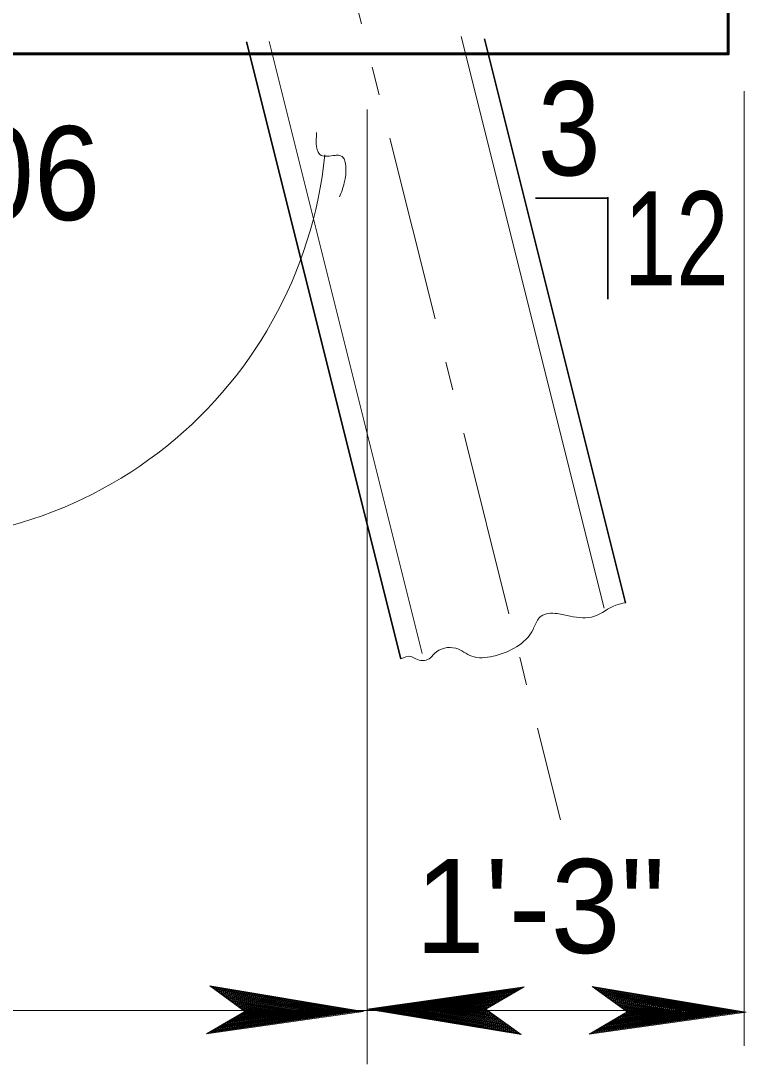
# Model space of a CAD drawing. Extents: x 144 to 252, y 360 to 425.
# Drawn here: x 195.351 to 197.883, y 388.875 to 392.519 of the extents above; entities that cross this region are included whole.
import ezdxf
from ezdxf.enums import TextEntityAlignment as Align

# ---------------------------------------------------------------- set-up
doc = ezdxf.new("R2010")
doc.units = 0
doc.header["$LTSCALE"] = 0.13
doc.linetypes.add('DOT_DASHED', pattern=[7.7, 5, -1.2, 0.3, -1.2])
for name, color, linetype, lineweight in [('1', 7, 'Continuous', 40), ('14', 7, 'Continuous', 13), ('16', 7, 'Continuous', 13), ('3', 7, 'Continuous', 13), ('5', 7, 'Continuous', 35)]:
    doc.layers.add(name, color=color, linetype=linetype, lineweight=lineweight)

msp = doc.modelspace()

# ---------------------------------------------------------------- linework, layer by layer
at = {"layer": '1', "lineweight": 60}
msp.add_lwpolyline([(189.8208, 392.4032), (197.8208, 392.4032), (197.8208, 394.4032), (194.0708, 394.4032), (194.0708, 394.6532), (193.5708, 394.6532), (193.5708, 394.4032), (189.8208, 394.4032)], dxfattribs=at)
at = {"layer": '16', "lineweight": 35}
for p, q in [((197.1477, 391.8999), (197.3977, 391.8999)), ((197.4002, 391.9027), (197.4002, 391.5464))]:
    msp.add_line(p, q, dxfattribs=at)
at = {"layer": '16'}
msp.add_arc((194.9206, 392.2022), 1.4992, 260.3949, 354.2102, dxfattribs=at)
msp.add_spline([(196.4637, 391.9044), (196.4797, 391.9526), (196.4637, 392.0489), (196.4476, 392.0489), (196.3994, 392.0489), (196.3833, 392.1293)], degree=3, dxfattribs=at)
at = {"layer": '3'}
for p, q in [((197.8766, 388.9398), (197.8766, 392.2738)), ((196.56, 388.8755), (196.56, 392.2095)), ((196.5476, 389.0595), (196.0099, 389.1488)), ((196.0099, 389.1488), (196.1324, 389.0597)), ((196.5332, 389.0602), (196.0132, 389.1464)), ((196.5223, 389.0602), (196.0164, 389.1441)), ((196.5079, 389.0602), (196.0207, 389.1409)), ((197.1083, 389.1457), (196.5596, 389.0679)), ((197.1023, 389.1422), (196.574, 389.0673)), ((196.9748, 389.0677), (197.1083, 389.1457)), ((197.8834, 389.0574), (197.3457, 389.1467)), ((197.3457, 389.1467), (197.4682, 389.0576)), ((197.869, 389.0581), (197.349, 389.1443)), ((197.8582, 389.0581), (197.3522, 389.142)), ((196.4952, 389.0602), (196.0244, 389.1382)), ((196.4838, 389.0602), (196.0277, 389.1358)), ((196.4694, 389.0602), (196.032, 389.1327)), ((196.4567, 389.0602), (196.0358, 389.1299)), ((196.4429, 389.0602), (196.0398, 389.127)), ((196.4291, 389.0602), (196.0439, 389.124)), ((196.4158, 389.0602), (196.0478, 389.1212)), ((196.4019, 389.0602), (196.0519, 389.1182)), ((196.3893, 389.0602), (196.0557, 389.1155)), ((196.3779, 389.0602), (196.0591, 389.113)), ((196.3622, 389.0602), (196.0637, 389.1097)), ((196.3484, 389.0602), (196.0677, 389.1067)), ((197.0988, 389.1402), (196.5848, 389.0673)), ((197.0942, 389.1375), (196.5992, 389.0673)), ((197.0902, 389.1351), (196.612, 389.0673)), ((197.0902, 389.1351), (196.612, 389.0673)), ((197.0865, 389.1329), (196.6233, 389.0673)), ((197.0819, 389.1302), (196.6377, 389.0673)), ((197.0778, 389.1278), (196.6505, 389.0673)), ((197.0734, 389.1253), (196.6642, 389.0673)), ((197.069, 389.1227), (196.6781, 389.0673)), ((197.0648, 389.1202), (196.6913, 389.0673)), ((197.0602, 389.1176), (196.7053, 389.0673)), ((197.0563, 389.1153), (196.7178, 389.0673)), ((197.0525, 389.1131), (196.7293, 389.0673)), ((197.0475, 389.1103), (196.7449, 389.0673)), ((197.0431, 389.1076), (196.7587, 389.0673)), ((197.0391, 389.1053), (196.7783, 389.0683)), ((197.8438, 389.0581), (197.3565, 389.1388)), ((197.831, 389.0581), (197.3602, 389.1362)), ((197.8197, 389.0581), (197.3636, 389.1337)), ((197.8053, 389.0581), (197.3678, 389.1306)), ((197.7925, 389.0581), (197.3716, 389.1278)), ((197.7788, 389.0581), (197.3757, 389.1249)), ((197.7649, 389.0581), (197.3798, 389.1219)), ((197.7517, 389.0581), (197.3837, 389.1191)), ((197.7378, 389.0581), (197.3877, 389.1161)), ((197.7252, 389.0581), (197.3915, 389.1134)), ((197.7138, 389.0581), (197.3949, 389.1109)), ((197.6981, 389.0581), (197.3995, 389.1076)), ((197.6842, 389.0581), (197.4036, 389.1046)), ((196.3304, 389.0607), (196.072, 389.1036)), ((196.3165, 389.0607), (196.0762, 389.1006)), ((196.3033, 389.0607), (196.08, 389.0977)), ((196.2943, 389.0602), (196.0837, 389.095)), ((196.2823, 389.0602), (196.0873, 389.0924)), ((196.2684, 389.0602), (196.0914, 389.0894)), ((196.2527, 389.0602), (196.0961, 389.0862)), ((196.2402, 389.0602), (196.0998, 389.0834)), ((196.2269, 389.0602), (196.1037, 389.0806)), ((196.2149, 389.0602), (196.1072, 389.0779)), ((196.2004, 389.0602), (196.1115, 389.0749)), ((196.1866, 389.0602), (196.1157, 389.0719)), ((196.1739, 389.0602), (196.1193, 389.0692)), ((197.0359, 389.1034), (196.7767, 389.0668)), ((197.0315, 389.1008), (196.7907, 389.0668)), ((197.0272, 389.0983), (196.8038, 389.0668)), ((197.0257, 389.0975), (196.8129, 389.0673)), ((197.0218, 389.0952), (196.8249, 389.0673)), ((197.0174, 389.0926), (196.8388, 389.0673)), ((197.0124, 389.0897), (196.8544, 389.0673)), ((197.0083, 389.0873), (196.867, 389.0673)), ((197.0041, 389.0848), (196.8802, 389.0673)), ((197.0002, 389.0826), (196.8922, 389.0673)), ((196.9956, 389.0799), (196.9067, 389.0673)), ((196.9912, 389.0773), (196.9206, 389.0673)), ((196.9871, 389.075), (196.9332, 389.0673)), ((196.9818, 389.0719), (196.9567, 389.0683)), ((196.9792, 389.0703), (196.9579, 389.0673)), ((197.6662, 389.0586), (197.4078, 389.1015)), ((197.6523, 389.0586), (197.412, 389.0985)), ((197.6392, 389.0586), (197.4158, 389.0957)), ((197.6301, 389.0581), (197.4196, 389.0929)), ((197.6181, 389.0581), (197.4232, 389.0903)), ((197.6043, 389.0581), (197.4272, 389.0873)), ((197.5886, 389.0581), (197.4319, 389.0841)), ((197.576, 389.0581), (197.4356, 389.0813)), ((197.5627, 389.0581), (197.4395, 389.0785)), ((197.5507, 389.0581), (197.4431, 389.0758)), ((197.5362, 389.0581), (197.4473, 389.0728)), ((197.5224, 389.0581), (197.4515, 389.0698)), ((195.8124, 389.0625), (189.8297, 389.0625)), ((197.8124, 389.0625), (191.8297, 389.0625)), ((196.1324, 389.0597), (195.9988, 388.9817)), ((195.9988, 388.9817), (196.5476, 389.0595)), ((196.0048, 388.9853), (196.5332, 389.0602)), ((196.0083, 388.9872), (196.5223, 389.0602)), ((196.0129, 388.9899), (196.5079, 389.0602)), ((196.017, 388.9923), (196.4952, 389.0602)), ((196.017, 388.9923), (196.4952, 389.0602)), ((196.0207, 388.9945), (196.4838, 389.0602)), ((196.0252, 388.9972), (196.4694, 389.0602)), ((196.0293, 388.9996), (196.4567, 389.0602)), ((196.0337, 389.0021), (196.4429, 389.0602)), ((196.0382, 389.0047), (196.4291, 389.0602)), ((196.0424, 389.0072), (196.4158, 389.0602)), ((196.0469, 389.0098), (196.4019, 389.0602)), ((196.0509, 389.0121), (196.3893, 389.0602)), ((196.0547, 389.0143), (196.3779, 389.0602)), ((196.0597, 389.0172), (196.3622, 389.0602)), ((196.0641, 389.0198), (196.3484, 389.0602)), ((196.0681, 389.0221), (196.3288, 389.0591)), ((196.0712, 389.024), (196.3304, 389.0607)), ((196.0757, 389.0266), (196.3165, 389.0607)), ((196.0799, 389.0291), (196.3033, 389.0607)), ((196.0814, 389.0299), (196.2943, 389.0602)), ((196.0853, 389.0322), (196.2823, 389.0602)), ((196.0897, 389.0348), (196.2684, 389.0602)), ((196.0948, 389.0377), (196.2527, 389.0602)), ((196.0988, 389.0401), (196.2402, 389.0602)), ((196.1031, 389.0426), (196.2269, 389.0602)), ((196.1069, 389.0448), (196.2149, 389.0602)), ((196.1116, 389.0475), (196.2004, 389.0602)), ((196.116, 389.0501), (196.1866, 389.0602)), ((196.1201, 389.0524), (196.1739, 389.0602)), ((196.1607, 389.0602), (196.1232, 389.0663)), ((196.1253, 389.0555), (196.1504, 389.0591)), ((196.1492, 389.0602), (196.1267, 389.0639)), ((196.128, 389.0571), (196.1492, 389.0602)), ((196.1391, 389.0602), (196.1297, 389.0617)), ((196.1322, 389.0595), (196.5476, 389.0595)), ((196.5596, 389.0679), (197.0973, 388.9787)), ((196.975, 389.0679), (196.5596, 389.0679)), ((196.574, 389.0673), (197.094, 388.981)), ((196.5848, 389.0673), (197.0907, 388.9833)), ((196.5992, 389.0673), (197.0865, 388.9865)), ((196.612, 389.0673), (197.0828, 388.9892)), ((196.6233, 389.0673), (197.0794, 388.9916)), ((196.6377, 389.0673), (197.0752, 388.9948)), ((196.6505, 389.0673), (197.0714, 388.9975)), ((196.6642, 389.0673), (197.0673, 389.0004)), ((196.6781, 389.0673), (197.0632, 389.0034)), ((196.6913, 389.0673), (197.0593, 389.0062)), ((196.7053, 389.0673), (197.0553, 389.0093)), ((196.7178, 389.0673), (197.0515, 389.0119)), ((196.7293, 389.0673), (197.0481, 389.0144)), ((196.7449, 389.0673), (197.0435, 389.0177)), ((196.7587, 389.0673), (197.0394, 389.0207)), ((196.7767, 389.0668), (197.0352, 389.0238)), ((196.7907, 389.0668), (197.031, 389.0268)), ((196.8038, 389.0668), (197.0272, 389.0297)), ((196.8129, 389.0673), (197.0234, 389.0324)), ((196.8249, 389.0673), (197.0198, 389.035)), ((196.8388, 389.0673), (197.0157, 389.038)), ((196.8544, 389.0673), (197.0111, 389.0412)), ((196.867, 389.0673), (197.0074, 389.044)), ((196.8802, 389.0673), (197.0035, 389.0468)), ((196.8922, 389.0673), (196.9999, 389.0495)), ((196.9067, 389.0673), (196.9957, 389.0525)), ((196.9206, 389.0673), (196.9915, 389.0555)), ((196.9332, 389.0673), (196.9878, 389.0582)), ((196.9465, 389.0673), (196.9839, 389.0611)), ((196.9579, 389.0673), (196.9805, 389.0635)), ((196.9681, 389.0673), (196.9775, 389.0657)), ((197.0973, 388.9787), (196.9748, 389.0677)), ((197.4682, 389.0576), (197.3347, 388.9797)), ((197.3347, 388.9797), (197.8834, 389.0574)), ((197.3407, 388.9832), (197.869, 389.0581)), ((197.3442, 388.9852), (197.8582, 389.0581)), ((197.3487, 388.9878), (197.8438, 389.0581)), ((197.3528, 388.9903), (197.831, 389.0581)), ((197.3528, 388.9903), (197.831, 389.0581)), ((197.3565, 388.9924), (197.8197, 389.0581)), ((197.3611, 388.9951), (197.8053, 389.0581)), ((197.3652, 388.9975), (197.7925, 389.0581)), ((197.3696, 389), (197.7788, 389.0581)), ((197.374, 389.0026), (197.7649, 389.0581)), ((197.3782, 389.0051), (197.7517, 389.0581)), ((197.3827, 389.0077), (197.7378, 389.0581)), ((197.3868, 389.01), (197.7252, 389.0581)), ((197.3905, 389.0122), (197.7138, 389.0581)), ((197.3955, 389.0151), (197.6981, 389.0581)), ((197.3999, 389.0177), (197.6842, 389.0581)), ((197.4039, 389.02), (197.6647, 389.057)), ((197.4071, 389.0219), (197.6662, 389.0586)), ((197.4115, 389.0245), (197.6523, 389.0586)), ((197.4158, 389.027), (197.6392, 389.0586)), ((197.4172, 389.0278), (197.6301, 389.0581)), ((197.4212, 389.0301), (197.6181, 389.0581)), ((197.4256, 389.0327), (197.6043, 389.0581)), ((197.4306, 389.0356), (197.5886, 389.0581)), ((197.4347, 389.038), (197.576, 389.0581)), ((197.4389, 389.0405), (197.5627, 389.0581)), ((197.4427, 389.0428), (197.5507, 389.0581)), ((197.4474, 389.0454), (197.5362, 389.0581)), ((197.4518, 389.048), (197.5224, 389.0581)), ((197.5097, 389.0581), (197.4552, 389.0671)), ((197.4559, 389.0503), (197.5097, 389.0581)), ((197.4965, 389.0581), (197.4591, 389.0642)), ((197.4612, 389.0534), (197.4862, 389.057)), ((197.4851, 389.0581), (197.4625, 389.0618)), ((197.4638, 389.055), (197.4851, 389.0581)), ((197.4749, 389.0581), (197.4655, 389.0596)), ((197.468, 389.0574), (197.8834, 389.0574))]:
    msp.add_line(p, q, dxfattribs=at)
at = {"layer": '5', "linetype": 'DOT_DASHED', "lineweight": 13}
msp.add_line((196.1246, 394.1696), (197.2347, 389.7283), dxfattribs=at)
at = {"layer": '5', "lineweight": 13}
for p, q in [((196.8886, 392.4637), (197.3874, 390.4681)), ((196.2175, 392.4472), (196.7519, 390.3092))]:
    msp.add_line(p, q, dxfattribs=at)
at = {"layer": '5'}
for p, q in [((196.9693, 392.4566), (197.4617, 390.4867)), ((196.139, 392.4454), (196.6776, 390.2907))]:
    msp.add_line(p, q, dxfattribs=at)
at = {"layer": '5', "lineweight": 13}
msp.add_spline([(197.4617, 390.4867), (197.4278, 390.4782), (197.3533, 390.4396), (197.2694, 390.4396), (197.2229, 390.4489), (197.1671, 390.4396), (197.1577, 390.4303), (197.1392, 390.3931), (197.1205, 390.3652), (197.0554, 390.3186), (196.9995, 390.3), (196.9251, 390.3), (196.8692, 390.3279), (196.7947, 390.3093), (196.7762, 390.2907), (196.7296, 390.2907), (196.7115, 390.2992), (196.6776, 390.2907)], degree=3, dxfattribs=at)

# ---------------------------------------------------------------- texts
at = {"layer": '14', "width": 0.95}
msp.add_text('P806', height=0.3281, dxfattribs=at).set_placement((195.1412, 391.8231), align=Align.CENTER)
at = {"layer": '16', "width": 0.9}
msp.add_text('3', height=0.3281, dxfattribs=at).set_placement((197.2655, 391.9793), align=Align.CENTER)
at = {"layer": '16', "width": 0.75}
msp.add_text('12', height=0.3281, dxfattribs=at).set_placement((197.8222, 391.5953), align=Align.RIGHT)
at = {"layer": '16'}
msp.add_text('1\'-3"', height=0.3281, dxfattribs=at).set_placement((197.1639, 389.2637), align=Align.CENTER)

doc.saveas('drawing.dxf')
